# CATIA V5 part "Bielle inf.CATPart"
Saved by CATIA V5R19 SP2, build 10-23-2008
Part number: Bielle
Publications: "diamètre bielle", "Longueur bielle"
Bounding box of the stored display mesh (mm): x -5 to 5, y -10 to 210, z -10 to 10
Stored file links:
  C:\Users\pierre\Documents\IFMA\IAO\Bielle inf.CATPart
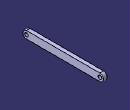
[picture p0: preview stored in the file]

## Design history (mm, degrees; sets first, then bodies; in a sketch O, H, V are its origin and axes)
Parameters
  `diamètre bielle` = 20 mm
  `Longueur bielle` = 200 mm
Body1 (main body)
  Point1: stored without definition
  Point2: stored without definition
  Sketch1 on yz-plane, origin (0, 0, 0), H (0, 1, 0), V (0, 0, 1)
    line L1 (200, 10) -> (0, 10)
    line L2 (0, -10) -> (200, -10)
    arc A1 centre (200, 0) radius 10 from (200, 10) to (200, -10) cw
    point P5 (200, 0)
    arc A2 centre (0, 0) radius 10 from (0, 10) to (0, -10) ccw
    point P6 (0, 0)
    reference projected point E1 (0, 0) from Point7
    reference projected point E2 (200, 0) from Point1
    distance L1 L2 = 20 {= `diamètre bielle`}
    tangency: A1 L2, A1 L1, A2 L1, L2 A2
    coincidence: P6 E1, P5 E2
  Pad1: profile Sketch1, direction (1, 0, 0), length 5, mirrored extent
  Point3: stored without definition
  Point4: stored without definition
  Sketch2 on yz-plane, origin (0, 0, 0), H (0, 1, 0), V (0, 0, 1)
    circle A1 centre (200, 0) radius 5
    point P1 (200, 0)
    circle A2 centre (0, 0) radius 5
    point P2 (0, 0)
    reference projected line E1 (200, 10) -> (-3.6735, 10) from edge [face of Pad1 from Sketch1.L1 | end face of Pad1]
    reference projected point E2 (0, 0) from Point4
    reference projected line E3 (203.6735, 10) -> (0, 10) from edge [face of Pad1 from Sketch1.L1 | end face of Pad1]
    reference projected point E4 (200, 0) from Point1
    distance A1 E1 = 5
    distance A2 E3 = 5
    coincidence: E2 P2, E4 P1
  Pocket1: profile Sketch2, direction (-1, 0, 0), through (limit type 6), opposite side length 5
  Point5: (0, 0, 0)
  Point6: (0, 200, 0)
  Line1: type PtPt, FirstPoint Point5, SecondPoint Point6
  Plane1: type OffsetPt, RefPlane yz-plane, RefPoint Point5
  Point7: stored without definition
